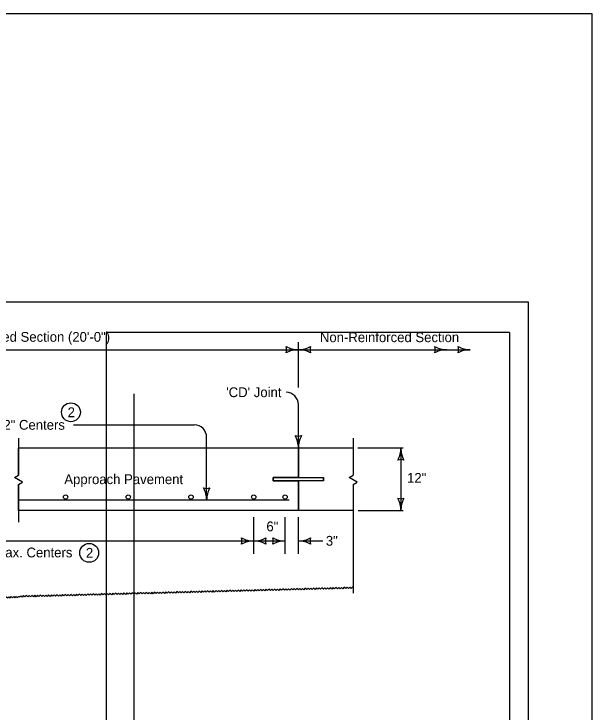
# Model space of a CAD drawing. Extents: x -2135039 to -2124495, y -2139046 to -2132546.
# Drawn here: x -2132638 to -2131695, y -2133685 to -2132546 of the extents above; entities that cross this region are included whole.
import ezdxf

# ---------------------------------------------------------------- set-up
doc = ezdxf.new("R2010")
doc.units = 0
for name, color, linetype in [('BridgeSuperStructureExisting', 7, 'Continuous'), ('dsnAlignmentStation', 7, 'Continuous'), ('dsnCellElements', 7, 'Continuous'), ('dsnStdLabel', 7, 'Continuous'), ('dsnStdLineWork', 7, 'Continuous'), ('PhoEdgeShoulderPaved', 7, 'Continuous')]:
    doc.layers.add(name, color=color, linetype=linetype)

msp = doc.modelspace()

# ---------------------------------------------------------------- linework, layer by layer
at = {"layer": 'BridgeSuperStructureExisting'}
for p, q in [((-2132630.7, -2133238.6), (-2132630.7, -2133298.7)), ((-2132084.4, -2133238.6), (-2132084.4, -2133298.7)), ((-2132174, -2133302.6), (-2132174, -2133254.3)), ((-2132214.9, -2133308.3), (-2132214.9, -2133302.6)), ((-2132214.9, -2133302.6), (-2132133.1, -2133302.6)), ((-2132133.1, -2133302.6), (-2132133.1, -2133308.3)), ((-2132630.7, -2133313.9), (-2132630.7, -2133375.4)), ((-2132133.1, -2133308.3), (-2132214.9, -2133308.3)), ((-2132174, -2133356.6), (-2132174, -2133308.3)), ((-2132084.4, -2133313.9), (-2132084.4, -2133491.1)), ((-2132189.1, -2133339.5), (-2132630.7, -2133339.5))]:
    msp.add_line(p, q, dxfattribs=at)
for points in [[(-2132630.7, -2133313.9), (-2132624.1, -2133310.1), (-2132637.3, -2133302.5), (-2132630.7, -2133298.7)], [(-2132084.4, -2133313.9), (-2132077.9, -2133310.1), (-2132091, -2133302.5), (-2132084.4, -2133298.7)]]:
    msp.add_lwpolyline(points, dxfattribs=at)
for centre, radius in [((-2132545.1, -2133196.2), 15.4), ((-2132553.8, -2133334.6), 3.55), ((-2132451.5, -2133334.6), 3.55), ((-2132349.2, -2133334.6), 3.55), ((-2132246.9, -2133334.6), 3.55), ((-2132195.8, -2133334.6), 3.55), ((-2132515.3, -2133425.5), 15.4)]:
    msp.add_circle(centre, radius, dxfattribs=at)
for centre, radius, start, end in [((-2132049.3, -2133254.3), 42.5, 331.9275, 360), ((-2132049.3, -2133254.3), 42.5, 331.9275, 360), ((-2131964.3, -2133254.3), 42.5, 180, 208.0725), ((-2131964.3, -2133254.3), 42.5, 180, 208.0725), ((-2132006.8, -2133289.9), 16.4, 72.2666, 107.7334), ((-2132006.8, -2133289.9), 16.4, 72.2666, 107.7334), ((-2132006.8, -2133320.9), 16.4, 252.2666, 287.7333), ((-2132049.3, -2133356.6), 42.5, 360, 28.0725), ((-2131964.3, -2133356.6), 42.5, 151.9275, 180)]:
    msp.add_arc(centre, radius, start, end, dxfattribs=at)
at = {"layer": 'dsnAlignmentStation'}
msp.add_lwpolyline([(-2134934.4, -2133016), (-2131799.4, -2133016), (-2131799.4, -2135026), (-2134934.4, -2135026)], close=True, dxfattribs=at)
at = {"layer": 'dsnCellElements'}
for centre, radius, start, end in [((-2132209.6, -2133094.1), 16.4, 342.2666, 17.7333), ((-2132174, -2133051.6), 42.5, 241.9275, 270), ((-2132174, -2133051.6), 42.5, 270, 298.0725), ((-2132138.4, -2133094.1), 16.4, 162.2666, 197.7334), ((-2131967.3, -2133094.1), 16.4, 342.2666, 17.7333), ((-2131931.7, -2133051.6), 42.5, 241.9275, 270), ((-2131929.2, -2133094.1), 16.4, 342.2666, 17.7333), ((-2131893.5, -2133051.6), 42.5, 241.9275, 270), ((-2132174, -2133136.6), 42.5, 90, 118.0725), ((-2132174, -2133136.6), 42.5, 61.9275, 90), ((-2131931.7, -2133136.6), 42.5, 90, 118.0725), ((-2131893.5, -2133136.6), 42.5, 90, 118.0725), ((-2132174, -2133218.6), 16.4, 252.2666, 287.7333), ((-2132216.5, -2133254.3), 42.5, 360, 28.0725), ((-2132131.5, -2133254.3), 42.5, 151.9275, 180), ((-2132323.7, -2133303.9), 16.4, 252.2666, 287.7333), ((-2132366.2, -2133339.5), 42.5, 360, 28.0725), ((-2132281.2, -2133339.5), 42.5, 151.9275, 180), ((-2132282.6, -2133406.2), 16.4, 342.2666, 17.7333), ((-2132246.9, -2133363.7), 42.5, 241.9275, 270), ((-2132246.9, -2133448.7), 42.5, 90, 118.0725), ((-2132246.9, -2133363.7), 42.5, 270, 298.0725), ((-2132246.9, -2133448.7), 42.5, 61.9275, 90), ((-2132211.3, -2133406.2), 16.4, 162.2666, 197.7334), ((-2132231.4, -2133406.2), 16.4, 342.2666, 17.7333), ((-2132195.8, -2133363.7), 42.5, 241.9275, 270), ((-2132195.8, -2133448.7), 42.5, 90, 118.0725), ((-2132174, -2133363.7), 42.5, 270, 298.0725), ((-2132174, -2133448.7), 42.5, 61.9275, 90), ((-2132138.4, -2133406.2), 16.4, 162.2666, 197.7334)]:
    msp.add_arc(centre, radius, start, end, dxfattribs=at)
at = {"layer": 'dsnStdLabel'}
for p, q in [((-2132174, -2133155.7), (-2132174, -2133082)), ((-2133142.6, -2133094.1), (-2132174, -2133094.1)), ((-2132174, -2133094.1), (-2131893.5, -2133094.1)), ((-2132174, -2133254.3), (-2132174, -2133183.7)), ((-2132541, -2133216.7), (-2132343.9, -2133216.7)), ((-2132323.7, -2133339.5), (-2132323.7, -2133236.9)), ((-2132630.7, -2133298.7), (-2132630.7, -2133254.3)), ((-2132630.7, -2133254.3), (-2132174, -2133254.3)), ((-2132630.7, -2133254.3), (-2132174, -2133254.3)), ((-2132174, -2133254.3), (-2132174, -2133302.6)), ((-2132174, -2133254.3), (-2132084.9, -2133254.3)), ((-2132076.8, -2133254.3), (-2132003, -2133254.3)), ((-2132006.8, -2133254.3), (-2132006.8, -2133356.6)), ((-2132630.7, -2133298.7), (-2132630.7, -2133298.7)), ((-2132174, -2133302.6), (-2132214.9, -2133302.6)), ((-2132214.9, -2133302.6), (-2132214.9, -2133308.3)), ((-2132214.9, -2133302.6), (-2132214.9, -2133308.3)), ((-2132133.1, -2133308.3), (-2132133.1, -2133302.6)), ((-2132630.7, -2133356.6), (-2132630.7, -2133313.9)), ((-2132214.9, -2133308.3), (-2132174, -2133308.3)), ((-2132174, -2133308.3), (-2132174, -2133356.6)), ((-2132174, -2133356.6), (-2132174, -2133308.3)), ((-2132174, -2133356.6), (-2132630.7, -2133356.6)), ((-2132174, -2133356.6), (-2132630.7, -2133356.6)), ((-2132084.4, -2133356.6), (-2132174, -2133356.6)), ((-2132076.3, -2133356.6), (-2132003, -2133356.6)), ((-2132246.9, -2133427), (-2132246.9, -2133367.1)), ((-2132195.8, -2133427), (-2132195.8, -2133367.1)), ((-2132174, -2133427), (-2132174, -2133367.1)), ((-2132246.9, -2133406.2), (-2133069.7, -2133406.2)), ((-2132195.8, -2133406.2), (-2132246.9, -2133406.2)), ((-2132134.2, -2133406.2), (-2132174, -2133406.2))]:
    msp.add_line(p, q, dxfattribs=at)
for points in [[(-2132630.7, -2133313.9), (-2132624.1, -2133310.1), (-2132637.3, -2133302.5), (-2132630.7, -2133298.7)], [(-2132411.9, -2133491), (-2132413.1, -2133489.8), (-2132415.3, -2133492.2), (-2132417.6, -2133490), (-2132419.8, -2133492.3), (-2132422.2, -2133490.1), (-2132424.4, -2133492.4), (-2132426.7, -2133490.2), (-2132428.9, -2133492.5), (-2132431.3, -2133490.3), (-2132433.5, -2133492.6), (-2132435.8, -2133490.4), (-2132438, -2133492.8), (-2132440.4, -2133490.6), (-2132442.6, -2133492.9), (-2132444.9, -2133490.7), (-2132447.1, -2133493), (-2132449.5, -2133490.8), (-2132451.7, -2133493.1), (-2132454, -2133490.9), (-2132456.3, -2133493.2), (-2132458.6, -2133491), (-2132460.8, -2133493.4), (-2132463.1, -2133491.1), (-2132465.4, -2133493.5), (-2132466.5, -2133492.4)], [(-2132357.3, -2133489.5), (-2132358.5, -2133488.4), (-2132360.7, -2133490.7), (-2132363, -2133488.5), (-2132365.2, -2133490.9), (-2132367.6, -2133488.7), (-2132369.8, -2133491), (-2132372.1, -2133488.8), (-2132374.3, -2133491.1), (-2132376.7, -2133488.9), (-2132378.9, -2133491.2), (-2132381.2, -2133489), (-2132383.4, -2133491.3), (-2132385.8, -2133489.1), (-2132388, -2133491.5), (-2132390.3, -2133489.2), (-2132392.5, -2133491.6), (-2132394.9, -2133489.4), (-2132397.1, -2133491.7), (-2132399.4, -2133489.5), (-2132401.6, -2133491.8), (-2132404, -2133489.6), (-2132406.2, -2133491.9), (-2132408.5, -2133489.7), (-2132410.7, -2133492.1), (-2132411.9, -2133491)], [(-2132302.7, -2133488.1), (-2132303.9, -2133487), (-2132306.1, -2133489.3), (-2132308.4, -2133487.1), (-2132310.6, -2133489.4), (-2132313, -2133487.2), (-2132315.2, -2133489.6), (-2132317.5, -2133487.3), (-2132319.7, -2133489.7), (-2132322.1, -2133487.5), (-2132324.3, -2133489.8), (-2132326.6, -2133487.6), (-2132328.8, -2133489.9), (-2132331.2, -2133487.7), (-2132333.4, -2133490), (-2132335.7, -2133487.8), (-2132337.9, -2133490.2), (-2132340.3, -2133487.9), (-2132342.5, -2133490.3), (-2132344.8, -2133488.1), (-2132347, -2133490.4), (-2132349.4, -2133488.2), (-2132351.6, -2133490.5), (-2132353.9, -2133488.3), (-2132356.1, -2133490.6), (-2132357.3, -2133489.5)], [(-2132248.1, -2133486.7), (-2132249.3, -2133485.6), (-2132251.5, -2133487.9), (-2132253.8, -2133485.7), (-2132256, -2133488), (-2132258.4, -2133485.8), (-2132260.6, -2133488.1), (-2132262.9, -2133485.9), (-2132265.1, -2133488.2), (-2132267.5, -2133486), (-2132269.7, -2133488.4), (-2132272, -2133486.2), (-2132274.2, -2133488.5), (-2132276.6, -2133486.3), (-2132278.8, -2133488.6), (-2132281.1, -2133486.4), (-2132283.3, -2133488.7), (-2132285.7, -2133486.5), (-2132287.9, -2133488.8), (-2132290.2, -2133486.6), (-2132292.4, -2133489), (-2132294.8, -2133486.8), (-2132297, -2133489.1), (-2132299.3, -2133486.9), (-2132301.5, -2133489.2), (-2132302.7, -2133488.1)], [(-2132193.5, -2133485.2), (-2132194.6, -2133484.1), (-2132196.9, -2133486.5), (-2132199.2, -2133484.3), (-2132201.4, -2133486.6), (-2132203.8, -2133484.4), (-2132206, -2133486.7), (-2132208.3, -2133484.5), (-2132210.5, -2133486.8), (-2132212.9, -2133484.6), (-2132215.1, -2133486.9), (-2132217.4, -2133484.7), (-2132219.6, -2133487.1), (-2132222, -2133484.9), (-2132224.2, -2133487.2), (-2132226.5, -2133485), (-2132228.7, -2133487.3), (-2132231.1, -2133485.1), (-2132233.3, -2133487.4), (-2132235.6, -2133485.2), (-2132237.8, -2133487.5), (-2132240.2, -2133485.3), (-2132242.4, -2133487.7), (-2132244.7, -2133485.4), (-2132246.9, -2133487.8), (-2132248.1, -2133486.7)], [(-2132138.9, -2133483.8), (-2132140, -2133482.7), (-2132142.3, -2133485), (-2132144.6, -2133482.8), (-2132146.8, -2133485.2), (-2132149.1, -2133482.9), (-2132151.4, -2133485.3), (-2132153.7, -2133483.1), (-2132155.9, -2133485.4), (-2132158.2, -2133483.2), (-2132160.5, -2133485.5), (-2132162.8, -2133483.3), (-2132165, -2133485.6), (-2132167.4, -2133483.4), (-2132169.6, -2133485.8), (-2132171.9, -2133483.5), (-2132174.1, -2133485.9), (-2132176.4, -2133483.7), (-2132178.7, -2133486), (-2132181, -2133483.8), (-2132183.2, -2133486.1), (-2132185.5, -2133483.9), (-2132187.8, -2133486.2), (-2132190.1, -2133484), (-2132192.3, -2133486.4), (-2132193.5, -2133485.2)], [(-2132084.3, -2133482.4), (-2132085.4, -2133481.3), (-2132087.7, -2133483.6), (-2132090, -2133481.4), (-2132092.2, -2133483.7), (-2132094.5, -2133481.5), (-2132096.8, -2133483.9), (-2132099.1, -2133481.6), (-2132101.3, -2133484), (-2132103.6, -2133481.8), (-2132105.9, -2133484.1), (-2132108.2, -2133481.9), (-2132110.4, -2133484.2), (-2132112.7, -2133482), (-2132115, -2133484.3), (-2132117.3, -2133482.1), (-2132119.5, -2133484.5), (-2132121.8, -2133482.2), (-2132124.1, -2133484.6), (-2132126.4, -2133482.4), (-2132128.6, -2133484.7), (-2132130.9, -2133482.5), (-2132133.2, -2133484.8), (-2132135.5, -2133482.6), (-2132137.7, -2133484.9), (-2132138.9, -2133483.8)], [(-2132667, -2133498.4), (-2132666.2, -2133497.5), (-2132664.1, -2133499.4), (-2132662.2, -2133497.4), (-2132660.2, -2133499.3), (-2132658.2, -2133497.3), (-2132656.2, -2133499.2), (-2132654.3, -2133497.2), (-2132652.2, -2133499.1), (-2132650.3, -2133497.1), (-2132648.3, -2133499), (-2132646.3, -2133497), (-2132644.3, -2133498.9), (-2132642.4, -2133496.9), (-2132640.3, -2133498.8), (-2132638.4, -2133496.8), (-2132636.4, -2133498.7), (-2132634.4, -2133496.7), (-2132632.4, -2133498.6), (-2132630.5, -2133496.6), (-2132629.5, -2133497.5)], [(-2132575.7, -2133495.2), (-2132576.9, -2133494.1), (-2132579.1, -2133496.5), (-2132581.5, -2133494.2), (-2132583.7, -2133496.6), (-2132586, -2133494.4), (-2132588.2, -2133496.7), (-2132590.6, -2133494.5), (-2132592.8, -2133496.8), (-2132595.1, -2133494.6), (-2132597.3, -2133496.9), (-2132599.7, -2133494.7), (-2132601.9, -2133497), (-2132604.2, -2133494.8), (-2132606.4, -2133497.2), (-2132608.8, -2133495), (-2132611, -2133497.3), (-2132613.3, -2133495.1), (-2132615.5, -2133497.4), (-2132617.9, -2133495.2), (-2132620.1, -2133497.5), (-2132622.4, -2133495.3), (-2132624.6, -2133497.6), (-2132627, -2133495.4), (-2132629.2, -2133497.8), (-2132630.3, -2133496.7)], [(-2132521.1, -2133493.8), (-2132522.3, -2133492.7), (-2132524.5, -2133495), (-2132526.8, -2133492.8), (-2132529.1, -2133495.1), (-2132531.4, -2133492.9), (-2132533.6, -2133495.3), (-2132535.9, -2133493.1), (-2132538.2, -2133495.4), (-2132540.5, -2133493.2), (-2132542.7, -2133495.5), (-2132545, -2133493.3), (-2132547.3, -2133495.6), (-2132549.6, -2133493.4), (-2132551.8, -2133495.7), (-2132554.1, -2133493.5), (-2132556.4, -2133495.9), (-2132558.7, -2133493.6), (-2132560.9, -2133496), (-2132563.2, -2133493.8), (-2132565.5, -2133496.1), (-2132567.8, -2133493.9), (-2132570, -2133496.2), (-2132572.4, -2133494), (-2132574.6, -2133496.3), (-2132575.7, -2133495.2)], [(-2132466.5, -2133492.4), (-2132467.7, -2133491.3), (-2132469.9, -2133493.6), (-2132472.2, -2133491.4), (-2132474.5, -2133493.7), (-2132476.8, -2133491.5), (-2132479, -2133493.8), (-2132481.3, -2133491.6), (-2132483.6, -2133494), (-2132485.9, -2133491.7), (-2132488.1, -2133494.1), (-2132490.4, -2133491.9), (-2132492.7, -2133494.2), (-2132495, -2133492), (-2132497.2, -2133494.3), (-2132499.5, -2133492.1), (-2132501.8, -2133494.4), (-2132504.1, -2133492.2), (-2132506.3, -2133494.6), (-2132508.6, -2133492.3), (-2132510.9, -2133494.7), (-2132513.2, -2133492.5), (-2132515.4, -2133494.8), (-2132517.7, -2133492.6), (-2132520, -2133494.9), (-2132521.1, -2133493.8)]]:
    msp.add_lwpolyline(points, dxfattribs=at)
for centre in [(-2132194.2, -2133183.7), (-2132343.9, -2133236.9)]:
    msp.add_arc(centre, 20.2, 0, 90, dxfattribs=at)
at = {"layer": 'dsnStdLineWork'}
msp.add_lwpolyline([(-2135038.9, -2135130.5), (-2131694.9, -2135130.5), (-2131694.9, -2132546.5), (-2135038.9, -2132546.5)], close=True, dxfattribs=at)
at = {"layer": 'PhoEdgeShoulderPaved'}
for p, q in [((-2132487.5, -2133066), (-2132487.5, -2134535.9)), ((-2131829.4, -2133066), (-2132487.5, -2133066)), ((-2131829.4, -2133066), (-2131829.4, -2134535.9)), ((-2132442.5, -2133166), (-2132442.5, -2134157.5))]:
    msp.add_line(p, q, dxfattribs=at)

# ---------------------------------------------------------------- texts
at = {"layer": 'dsnStdLabel'}
for s, p in [('Single Reinforced Section (20\'-0")', (-2132802.1, -2133081.2)), ('Non-Reinforced Section', (-2132138.9, -2133081.8)), ("'CD' Joint", (-2132291.8, -2133171.5)), ('2', (-2132550.5, -2133204.2)), ('#5 Bars At 12" Centers', (-2132773, -2133224.7)), ('Approach Pavement', (-2132555.9, -2133313.4)), ('12"', (-2131996.7, -2133311.2)), ('6"', (-2132226.2, -2133390.4)), ('3"', (-2132129.2, -2133413.9)), ('#5 Bars At 12" max. Centers', (-2132813.1, -2133432.9)), ('2', (-2132520.7, -2133433.5))]:
    msp.add_text(s, height=16, dxfattribs=at).set_placement(p)

doc.saveas('drawing.dxf')
